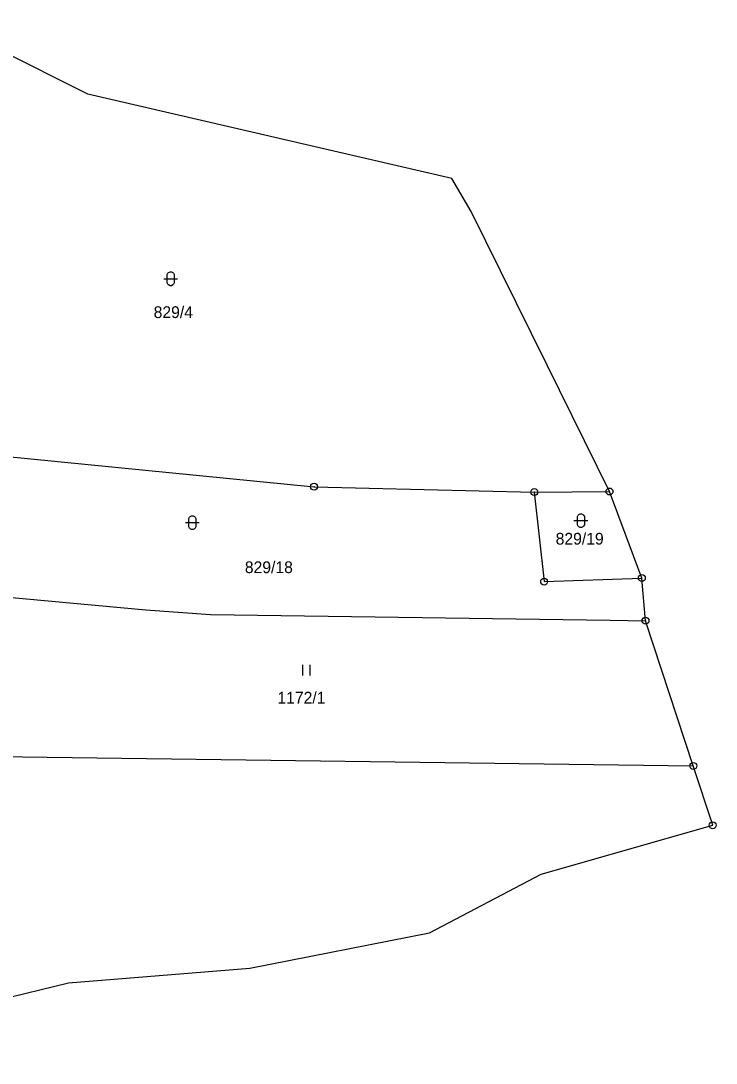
# Model space of a CAD drawing. Extents: x -796130 to -793145, y -1109506 to -1106267.
# Drawn here: x -793246.1 to -793145.5, y -1109258.5 to -1109107.7 of the extents above; entities that cross this region are included whole.
import ezdxf

# ---------------------------------------------------------------- set-up
doc = ezdxf.new("R2010")
doc.units = 0
for name, color, linetype in [('Vrstva 1', 7, 'Continuous'), ('Vrstva 14', 7, 'Continuous'), ('Vrstva 23', 7, 'Continuous'), ('Vrstva 28', 7, 'Continuous'), ('Vrstva 4', 7, 'Continuous')]:
    doc.layers.add(name, color=color, linetype=linetype)

msp = doc.modelspace()

# ---------------------------------------------------------------- linework, layer by layer
at = {"layer": 'Vrstva 1'}
for p, q in [((-793249.09, -1109170.59), (-793203.7, -1109175.06)), ((-793203.7, -1109175.06), (-793171.81, -1109175.84)), ((-793171.81, -1109175.84), (-793160.93, -1109175.76)), ((-793171.81, -1109175.84), (-793170.39, -1109188.79)), ((-793170.39, -1109188.79), (-793156.25, -1109188.28)), ((-793252.77, -1109190.63), (-793228.03, -1109192.87)), ((-793228.03, -1109192.87), (-793218.67, -1109193.57)), ((-793218.67, -1109193.57), (-793160.82, -1109194.38)), ((-793160.82, -1109194.38), (-793155.72, -1109194.45)), ((-793255.17, -1109214), (-793148.81, -1109215.46))]:
    msp.add_line(p, q, dxfattribs=at)
at = {"layer": 'Vrstva 23'}
for p, q in [((-793224.94, -1109144.38), (-793224.84, -1109144.18)), ((-793224.84, -1109144.18), (-793224.74, -1109144.08)), ((-793224.74, -1109144.08), (-793224.54, -1109143.98)), ((-793224.54, -1109143.98), (-793224.34, -1109143.98)), ((-793224.34, -1109143.98), (-793224.14, -1109144.08)), ((-793224.14, -1109144.08), (-793224.04, -1109144.18)), ((-793224.04, -1109144.18), (-793223.94, -1109144.38)), ((-793225.44, -1109144.98), (-793223.44, -1109144.98)), ((-793224.94, -1109145.58), (-793224.94, -1109144.38)), ((-793224.84, -1109145.78), (-793224.94, -1109145.58)), ((-793223.94, -1109145.58), (-793224.04, -1109145.78)), ((-793223.94, -1109144.38), (-793223.94, -1109145.58)), ((-793224.74, -1109145.88), (-793224.84, -1109145.78)), ((-793224.54, -1109145.98), (-793224.74, -1109145.88)), ((-793224.34, -1109145.98), (-793224.54, -1109145.98)), ((-793224.14, -1109145.88), (-793224.34, -1109145.98)), ((-793224.04, -1109145.78), (-793224.14, -1109145.88)), ((-793222.31, -1109180.26), (-793220.31, -1109180.26)), ((-793221.81, -1109179.66), (-793221.71, -1109179.46)), ((-793221.81, -1109180.86), (-793221.81, -1109179.66)), ((-793221.71, -1109179.46), (-793221.61, -1109179.36)), ((-793221.61, -1109179.36), (-793221.41, -1109179.26)), ((-793221.41, -1109179.26), (-793221.21, -1109179.26)), ((-793221.21, -1109179.26), (-793221.01, -1109179.36)), ((-793221.01, -1109179.36), (-793220.91, -1109179.46)), ((-793220.91, -1109179.46), (-793220.81, -1109179.66)), ((-793220.81, -1109179.66), (-793220.81, -1109180.86)), ((-793166.07, -1109179.97), (-793164.07, -1109179.97)), ((-793165.57, -1109179.37), (-793165.47, -1109179.17)), ((-793165.57, -1109180.57), (-793165.57, -1109179.37)), ((-793165.47, -1109179.17), (-793165.37, -1109179.07)), ((-793165.37, -1109179.07), (-793165.17, -1109178.97)), ((-793165.17, -1109178.97), (-793164.97, -1109178.97)), ((-793164.97, -1109178.97), (-793164.77, -1109179.07)), ((-793164.77, -1109179.07), (-793164.67, -1109179.17)), ((-793164.67, -1109179.17), (-793164.57, -1109179.37)), ((-793164.57, -1109179.37), (-793164.57, -1109180.57)), ((-793221.71, -1109181.06), (-793221.81, -1109180.86)), ((-793221.61, -1109181.16), (-793221.71, -1109181.06)), ((-793221.41, -1109181.26), (-793221.61, -1109181.16)), ((-793221.21, -1109181.26), (-793221.41, -1109181.26)), ((-793221.01, -1109181.16), (-793221.21, -1109181.26)), ((-793220.91, -1109181.06), (-793221.01, -1109181.16)), ((-793220.81, -1109180.86), (-793220.91, -1109181.06)), ((-793165.47, -1109180.77), (-793165.57, -1109180.57)), ((-793165.37, -1109180.87), (-793165.47, -1109180.77)), ((-793165.17, -1109180.97), (-793165.37, -1109180.87)), ((-793164.97, -1109180.97), (-793165.17, -1109180.97)), ((-793164.77, -1109180.87), (-793164.97, -1109180.97)), ((-793164.67, -1109180.77), (-793164.77, -1109180.87)), ((-793164.57, -1109180.57), (-793164.67, -1109180.77)), ((-793205.3, -1109202.36), (-793205.3, -1109200.86)), ((-793204.3, -1109200.86), (-793204.3, -1109202.36))]:
    msp.add_line(p, q, dxfattribs=at)
at = {"layer": 'Vrstva 28'}
for centre, radius in [((-793203.7, -1109175.06), 0.5), ((-793203.7, -1109175.06), 0.01), ((-793171.81, -1109175.84), 0.5), ((-793171.81, -1109175.84), 0.5), ((-793171.81, -1109175.84), 0.01), ((-793171.81, -1109175.84), 0.01), ((-793160.93, -1109175.76), 0.5), ((-793160.93, -1109175.76), 0.01), ((-793156.25, -1109188.28), 0.5), ((-793156.25, -1109188.28), 0.5), ((-793170.39, -1109188.79), 0.5), ((-793170.39, -1109188.79), 0.01), ((-793156.25, -1109188.28), 0.01), ((-793156.25, -1109188.28), 0.01), ((-793155.72, -1109194.45), 0.5), ((-793155.72, -1109194.45), 0.5), ((-793155.72, -1109194.45), 0.01), ((-793155.72, -1109194.45), 0.01), ((-793148.81, -1109215.46), 0.5), ((-793148.81, -1109215.46), 0.01), ((-793145.99, -1109224.05), 0.5), ((-793145.99, -1109224.05), 0.01)]:
    msp.add_circle(centre, radius, dxfattribs=at)
at = {"layer": 'Vrstva 4'}
for p, q in [((-793236.44, -1109118.27), (-793257.6, -1109107.66)), ((-793183.76, -1109130.47), (-793236.44, -1109118.27)), ((-793180.95, -1109135.24), (-793183.76, -1109130.47)), ((-793176.71, -1109143.82), (-793180.95, -1109135.24)), ((-793169.95, -1109157.5), (-793176.71, -1109143.82)), ((-793160.93, -1109175.76), (-793169.95, -1109157.5)), ((-793156.25, -1109188.28), (-793160.93, -1109175.76)), ((-793155.72, -1109194.45), (-793156.25, -1109188.28)), ((-793148.81, -1109215.46), (-793155.72, -1109194.45)), ((-793145.99, -1109224.05), (-793148.81, -1109215.46)), ((-793170.82, -1109231.14), (-793145.99, -1109224.05)), ((-793186.97, -1109239.62), (-793170.82, -1109231.14)), ((-793213, -1109244.74), (-793186.97, -1109239.62)), ((-793239.25, -1109246.83), (-793213, -1109244.74)), ((-793286.93, -1109258.47), (-793239.25, -1109246.83))]:
    msp.add_line(p, q, dxfattribs=at)

# ---------------------------------------------------------------- texts
at = {"layer": 'Vrstva 14'}
for s, p in [('829/4', (-793226.91, -1109150.66)), ('829/19', (-793168.723, -1109183.44)), ('829/18', (-793213.713, -1109187.57)), ('1172/1', (-793208.996, -1109206.44))]:
    msp.add_text(s, height=1.7, dxfattribs=at).set_placement(p)

doc.saveas('drawing.dxf')
